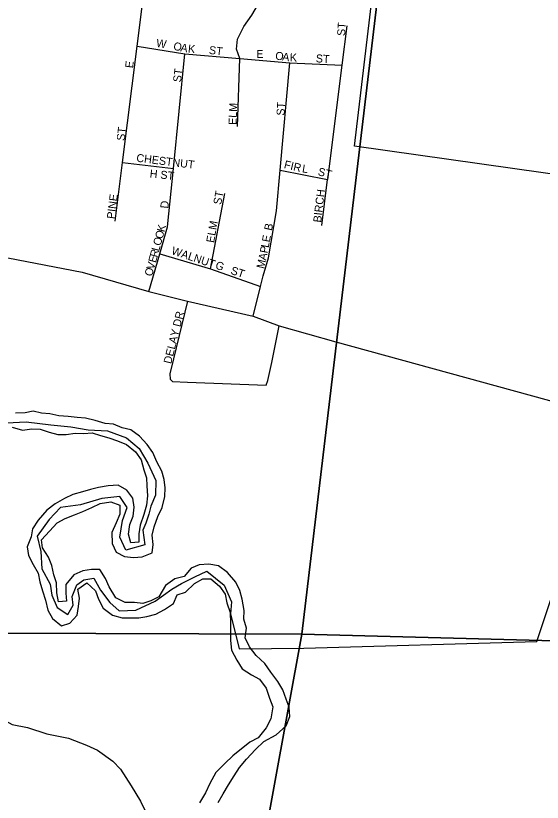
# Model space of a CAD drawing. Extents: x 1578669 to 1989827, y 208020 to 553079.
# Drawn here: x 1829075 to 1832363, y 385433 to 390343 of the extents above; entities that cross this region are included whole.
import ezdxf

# ---------------------------------------------------------------- set-up
doc = ezdxf.new("R2010")
doc.units = 0
for name, color, linetype in [('GM_X_City_Street', 7, 'Continuous'), ('GM_X_City_Street_Text', 7, 'Continuous'), ('GM_X_Corporation', 7, 'Continuous'), ('GM_X_Minor_River', 7, 'Continuous'), ('GM_X_Section', 7, 'Continuous'), ('GM_X_Township_Road', 7, 'Continuous')]:
    doc.layers.add(name, color=color, linetype=linetype)

msp = doc.modelspace()

# ---------------------------------------------------------------- linework, layer by layer
at = {"layer": 'GM_X_City_Street'}
for points in [[(1829696.5, 389059.2), (1829742.2, 389425.9), (1829833.5, 390153.2), (1829874.7, 390485.9), (1829905.7, 390808.6)], [(1830474.5, 390075), (1830452.9, 390133), (1830458.8, 390196.2), (1830499.6, 390275.4), (1830548.9, 390346.9), (1830591.6, 390416.3), (1830623.2, 390467.8), (1830636.5, 390599.1), (1830643.2, 390683.8), (1830624.2, 390811.5)], [(1831022.9, 389320.7), (1831112.9, 390034.2), (1831143.9, 390279.4)], [(1829833.5, 390153.2), (1830131.8, 390104.4), (1830474.5, 390075)], [(1829907, 388620.1), (1829974, 388857.2), (1830022.2, 389024.1), (1830059.2, 389388.3), (1830131.8, 390104.4)], [(1830460.1, 389651.6), (1830474.5, 390075)], [(1830474.5, 390075), (1830787.2, 390048), (1831112.9, 390034.2)], [(1830557.5, 388466.7), (1830603.8, 388652.6), (1830620.5, 388719.6), (1830653, 388830.9), (1830702.7, 389125.4), (1830725.9, 389378.4), (1830787.2, 390048)], [(1829742.2, 389425.9), (1830059.2, 389388.3)], [(1830725.9, 389378.4), (1831022.7, 389319.9)], [(1830986.5, 389033.1), (1831022.7, 389319.9), (1831022.9, 389320.7)], [(1830290.3, 388762.6), (1830381.5, 389233.3)], [(1828850.8, 388865.4), (1829488.9, 388741.1), (1829907, 388620.1), (1830147, 388560.8), (1830557.5, 388466.7), (1830719.8, 388407.1), (1831073.5, 388306.9), (1832491.5, 387917.7)], [(1829974, 388857.2), (1830290.3, 388762.6), (1830603.8, 388652.6)], [(1830147, 388560.8), (1830060.4, 388201.8), (1830037.5, 388106.2), (1830039.4, 388073.7), (1830052.8, 388060.3), (1830148.4, 388054.6), (1830638.6, 388036.7), (1830650, 388065.9), (1830674.1, 388178.8), (1830719.8, 388407.1)]]:
    msp.add_lwpolyline(points, dxfattribs=at)
at = {"layer": 'GM_X_Corporation'}
for points in [[(1833355.7, 389222.7), (1831189.9, 389528.6), (1831512.1, 392243.6)], [(1829017, 387802.2), (1829141, 387807.3), (1829294.9, 387788.2), (1829418.8, 387775.3), (1829526.7, 387758.5), (1829648.6, 387751.6), (1829766.3, 387706.7), (1829845.8, 387640.1), (1829899.1, 387549.6), (1829950.3, 387441.1), (1829947.6, 387349), (1829919.1, 387281.1), (1829906.8, 387231.2), (1829886.4, 387175.3), (1829868, 387131.3), (1829881.3, 387039.1), (1829763.1, 387006), (1829725.7, 387088.3), (1829742.5, 387192.3), (1829771.1, 387272.2), (1829725.6, 387340.6), (1829613.5, 387329.4), (1829479.2, 387290.3), (1829355.1, 387273.2), (1829284.5, 387197.6), (1829207.7, 387094), (1829231, 386997.8), (1829238.2, 386889.6), (1829289.5, 386795.1), (1829301, 386725), (1829334.4, 386648.6), (1829400.1, 386604.1), (1829434.5, 386663.9), (1829426.9, 386718), (1829455.5, 386789.9), (1829499.7, 386821.6), (1829561.8, 386831.2), (1829603.2, 386756.8), (1829662.7, 386680.3), (1829720.3, 386627.8), (1829824.3, 386631.1), (1829944.7, 386688.3), (1830049.3, 386763.6), (1830109.5, 386797.2), (1830193.9, 386840.7), (1830268.1, 386876.2), (1830375.5, 386787.3), (1830422.7, 386682.9), (1830416.1, 386608.8), (1830470.6, 386389.7), (1830873.2, 386393.7), (1832329.6, 386435.6), (1832784.8, 387808.1)]]:
    msp.add_lwpolyline(points, dxfattribs=at)
at = {"layer": 'GM_X_Minor_River'}
for points in [[(1830006.9, 387341.2), (1830008.3, 387395.2), (1830001.7, 387447.4), (1829987, 387499.9), (1829956.6, 387558.7), (1829930, 387615.5), (1829895.3, 387666.5), (1829846.7, 387717.8), (1829793.7, 387757.2), (1829740, 387770.6), (1829684.6, 387792.1), (1829632.7, 387797.4), (1829571.1, 387815), (1829509.5, 387830.6), (1829457.6, 387834), (1829401.8, 387841.5), (1829343.9, 387845), (1829288.2, 387856.4), (1829236.3, 387861.8), (1829184.6, 387873.1), (1829134.4, 387864.4), (1829074.3, 387862)], [(1829052, 387774.5), (1829117.5, 387754.7), (1829175.8, 387763.2), (1829227.7, 387761.9), (1829283.2, 387742.4), (1829336.9, 387729), (1829388.9, 387727.7), (1829445.1, 387736.2), (1829501.1, 387734.8), (1829551.2, 387739.5), (1829604.7, 387722.1), (1829656.3, 387706.7), (1829709.9, 387689.3), (1829767.3, 387665.8), (1829822.1, 387620.3), (1829858.8, 387569.3), (1829875.3, 387508.8), (1829892, 387458.3), (1829892.7, 387408.2), (1829897, 387346), (1829891.6, 387288.1), (1829874, 387228.5)], [(1829874, 387228.5), (1829852.3, 387163), (1829842.9, 387109.1), (1829843.6, 387057.1), (1829793.4, 387052.4), (1829778.9, 387106.8), (1829786.4, 387166.7), (1829807.7, 387218.2), (1829815.2, 387274.1), (1829806.6, 387330.4), (1829768, 387381.4), (1829714.8, 387412.8), (1829652.6, 387408.4), (1829592.4, 387398), (1829542, 387385.3), (1829491.6, 387370.6), (1829431.2, 387354.1), (1829378.6, 387329.5), (1829321.7, 387294.9), (1829268.7, 387256.2), (1829215, 387193.5), (1829179.6, 387140.4), (1829170.3, 387088.6), (1829146.7, 387027.1), (1829155.3, 386972.8), (1829183.9, 386916), (1829214.5, 386863.2), (1829225.1, 386808.8), (1829241.6, 386752.3), (1829260.1, 386693.8), (1829274.5, 386631.3), (1829305.2, 386580.5), (1829360, 386533), (1829412.4, 386549.6), (1829457.7, 386600.5), (1829467.1, 386654.3), (1829472.5, 386706.3), (1829461.9, 386762.6), (1829519, 386803.2), (1829573.6, 386751.7), (1829592.3, 386701.2), (1829620.9, 386644.4), (1829679.8, 386600.8), (1829739.3, 386583.2), (1829789.3, 386583.9), (1829843.4, 386584.5), (1829893.5, 386591.2), (1829949.9, 386605.8), (1830004.7, 386636.4), (1830059.7, 386673), (1830083.1, 386726.5), (1830135.5, 386745.1), (1830190.9, 386797.8), (1830243.7, 386826.4), (1830293.7, 386827.1), (1830346.5, 386781.7), (1830383.2, 386730.7), (1830393.9, 386678.4), (1830414.3, 386617.8), (1830416.6, 386553.6), (1830415.3, 386501.6), (1830415.7, 386441.5), (1830422.2, 386381.3), (1830454.6, 386320.3), (1830489.2, 386265.4), (1830546.2, 386227.8), (1830597.5, 386200.5), (1830638.1, 386145.4), (1830658.5, 386082.8), (1830681.1, 386028.1), (1830667.2, 385954.4), (1830637.7, 385897.1), (1830588.1, 385834.3), (1830537.4, 385807.6), (1830431.1, 385722.2), (1830379.9, 385673.5), (1830324.5, 385618.9), (1830286.7, 385549.8), (1830259.2, 385492.4), (1830221.5, 385429.3)], [(1830339.6, 385430.2), (1830371, 385485.5), (1830404.4, 385540.7), (1830437.9, 385597.9), (1830471.3, 385649.1), (1830516.6, 385702), (1830572.2, 385762.6), (1830623.5, 385811.3), (1830700.6, 385853.4), (1830764, 385909.8), (1830785.5, 385967.3), (1830783, 386025.5), (1830764.3, 386076), (1830741.8, 386134.7), (1830711.1, 386185.5), (1830668.7, 386244.7), (1830630.1, 386299.8), (1830575.4, 386349.2), (1830534.7, 386402.4), (1830508.2, 386459.1), (1830515.7, 386519), (1830499.2, 386575.5), (1830500.6, 386629.5), (1830488.4, 386699.9), (1830473.8, 386754.4), (1830449.2, 386807.1), (1830396.7, 386866.5), (1830341.8, 386908), (1830280.1, 386919.6), (1830220, 386915.1), (1830169.4, 386894.4), (1830126, 386841.5), (1830067.7, 386827), (1830010.6, 386786.4), (1829968.8, 386715.4), (1829918.1, 386690.7), (1829867.7, 386674), (1829815.8, 386679.3), (1829757.8, 386678.8), (1829700.5, 386708.4), (1829658.3, 386777.5), (1829635.7, 386830.2), (1829599.1, 386885.2), (1829547.1, 386884.6), (1829492.9, 386878), (1829438.2, 386851.3), (1829388.7, 386792.6), (1829387.3, 386738.5), (1829392, 386688.3), (1829341.9, 386683.6), (1829331.3, 386740), (1829328.9, 386802.1), (1829312.2, 386852.6), (1829299.7, 386911), (1829279.1, 386963.6), (1829242.6, 387020.6), (1829235.9, 387070.8), (1829285.3, 387125.6), (1829332.6, 387176.5), (1829383.3, 387203.2), (1829441.9, 387227.7), (1829494.5, 387248.4), (1829549.1, 387273), (1829601.8, 387297.6), (1829668, 387307.9), (1829725.5, 387286.4), (1829724, 387230.4), (1829702.7, 387176.9), (1829675.1, 387117.5), (1829677.3, 387047.4), (1829702, 386994.7), (1829753.3, 386967.3), (1829811.1, 386959.8), (1829865.2, 386964.4), (1829925.8, 386988.9), (1829933.2, 387040.7), (1829926.7, 387099), (1829940.1, 387152.7), (1829961.7, 387216.2), (1829989.2, 387273.6), (1830006.9, 387341.2)]]:
    msp.add_lwpolyline(points, dxfattribs=at)
at = {"layer": 'GM_X_Section'}
msp.add_lwpolyline([(1831546.7, 392238.4), (1830861.1, 386481.8), (1825067.6, 386500.8), (1825251.5, 390916.5)], dxfattribs=at)
for points in [[(1837357.5, 391978.5), (1837092.3, 386317.8), (1830861.1, 386481.8), (1831546.7, 392238.4)], [(1825067.6, 386500.8), (1830861.1, 386481.8), (1830333.1, 383580.3), (1830191.9, 380839), (1824860, 381080.1), (1824862.1, 381100)], [(1830861.1, 386481.8), (1837092.3, 386317.8), (1836858.2, 380466.9), (1835596.4, 380529), (1830191.9, 380839), (1830333.1, 383580.3)]]:
    msp.add_lwpolyline(points, close=True, dxfattribs=at)
at = {"layer": 'GM_X_Township_Road'}
msp.add_lwpolyline([(1828348.6, 386150.8), (1828355.3, 386141.3), (1828375.8, 386112.2), (1828450, 386070.2), (1828590.1, 386078.4), (1828684.2, 386098.5), (1828772.3, 386078.6), (1828850.5, 386020.5), (1828956.7, 385970.5), (1829052.9, 385918.5), (1829149, 385898.6), (1829269.2, 385860.6), (1829403.4, 385832.7), (1829517.6, 385788.8), (1829585.8, 385758.7), (1829682, 385688.7), (1829730.1, 385638.6), (1829796.3, 385534.5), (1829854.6, 385440.3), (1829914.8, 385316.1), (1829985.2, 385151.7)], dxfattribs=at)

# ---------------------------------------------------------------- texts
at = {"layer": 'GM_X_City_Street_Text'}
for s, rotation, p in [('ST', 86.1879, (1831131.1, 390215.1)), ('W', 351.2589, (1829949.5, 390149)), ('O', 347.6229, (1830055.8, 390131.2)), ('A', 349.7163, (1830100.7, 390121.4)), ('K', 354.8005, (1830148.8, 390112.9)), ('ST', 352.88, (1830279.3, 390105)), ('E', 0, (1830577.3, 390078.7)), ('O', 352.3707, (1830693, 390069.8)), ('A', 352.937, (1830737.1, 390063.9)), ('K', 358.1913, (1830785.8, 390058.1)), ('ST', 356.4262, (1830947.5, 390052.2)), ('E', 82.8514, (1829806.8, 390013.2)), ('ST', 82.88, (1830106, 389925.2)), ('ELM', 88.0261, (1830453.5, 389660.4)), ('ST', 86.4262, (1830752.7, 389717.8)), ('ST', 83.1614, (1829754, 389560)), ('CHESTNUT', 352.9723, (1829826.1, 389431.8)), ('FIR', 346.6047, (1830746.7, 389392)), ('H ST', 354.2923, (1829909.7, 389333)), ('L', 350.5298, (1830860.5, 389365.7)), ('ST', 345.0758, (1830958.1, 389348)), ('ST', 79.3721, (1830356.9, 389160.2)), ('BIRCH', 83.2095, (1830981.6, 389049.6)), ('PINE', 82.6521, (1829692.4, 389071.7)), ('D', 84.2937, (1830026.8, 389137.4)), ('K', 75.7322, (1830003.2, 388989)), ('ELM', 79.8732, (1830312.9, 388922.5)), ('B', 77.4763, (1830673.7, 388997.7)), ('O', 74.3888, (1829991, 388945.3)), ('O', 74.367, (1829979.2, 388903)), ('E', 79.0432, (1830660.5, 388925.9)), ('L', 74.3735, (1829969.7, 388869.1)), ('WALNUT', 341.5639, (1830043.5, 388855)), ('P', 79.0191, (1830647.1, 388856.7)), ('L', 79.0345, (1830653.8, 388891.3)), ('E', 74.3998, (1829949.5, 388797)), ('R', 74.3849, (1829959, 388830.9)), ('A', 77.8119, (1830637.6, 388812.6)), ('V', 74.3806, (1829937.7, 388754.6)), ('G', 338.7472, (1830316.7, 388766.8)), ('M', 76.8074, (1830625.4, 388760.2)), ('O', 74.3788, (1829925.8, 388712.3)), ('ST', 341.5607, (1830413.1, 388731.8)), ('DELAY DR', 75.9615, (1830045.2, 388166.2))]:
    msp.add_text(s, height=50, rotation=rotation, dxfattribs=at).set_placement(p)

doc.saveas('drawing.dxf')
